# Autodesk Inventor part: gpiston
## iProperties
Shininess: 86.0
Length Units: 11269
Angle Units: 11279
Time Units: 11290
Mass Units: 11283
Length Display Precision: 3
Angle Display Precision: 2
Compacted: True
Created: 2001-12
Part Number: gpiston
Material: Par défaut
Document SubType Name: Modélisation
Designer: pichon
Density: 1.0
Volumn: 71.431289465484
Area: 146.6376121522323
PropertySet Name: Model Information
Control State: 0
Master: False
Checked Out: False
Author: pichon
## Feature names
1. Révolution1 [Revolution]
2. Extrusion1
3. Chanfrein1 [Chamfer]
4. Révolution2 [Revolution]
